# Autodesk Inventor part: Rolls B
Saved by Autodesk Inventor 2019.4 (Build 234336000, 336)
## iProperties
Created: 2020-05
Part Number: Rolls B
Material: Generic
Document SubType Name: Modeling
Designer: Administrator
Density: 1 g/cm^3
Appearance: Default
Author: Administrator
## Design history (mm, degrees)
feature "Body2"
feature "Body3"
feature "Body4"
feature "Body21"
feature "Body22"
feature "Body23"
feature "Body24"
feature "Body25"
feature "Body26"
feature "Body29"
feature "Body30"
feature "Body31"
feature "Body33"
feature "Body34"
feature "Body35"
feature "Body36"
feature "Body37"
body "Solid1"
body "Solid2"
body "Solid3"
body "Solid4"
body "Solid5"
body "Solid6"
body "Solid7"
body "Solid8"
body "Solid9"
body "Solid10"
body "Solid11"
body "Solid12"
body "Solid13"
body "Solid14"
body "Solid15"
body "Solid16"
body "Solid17"
